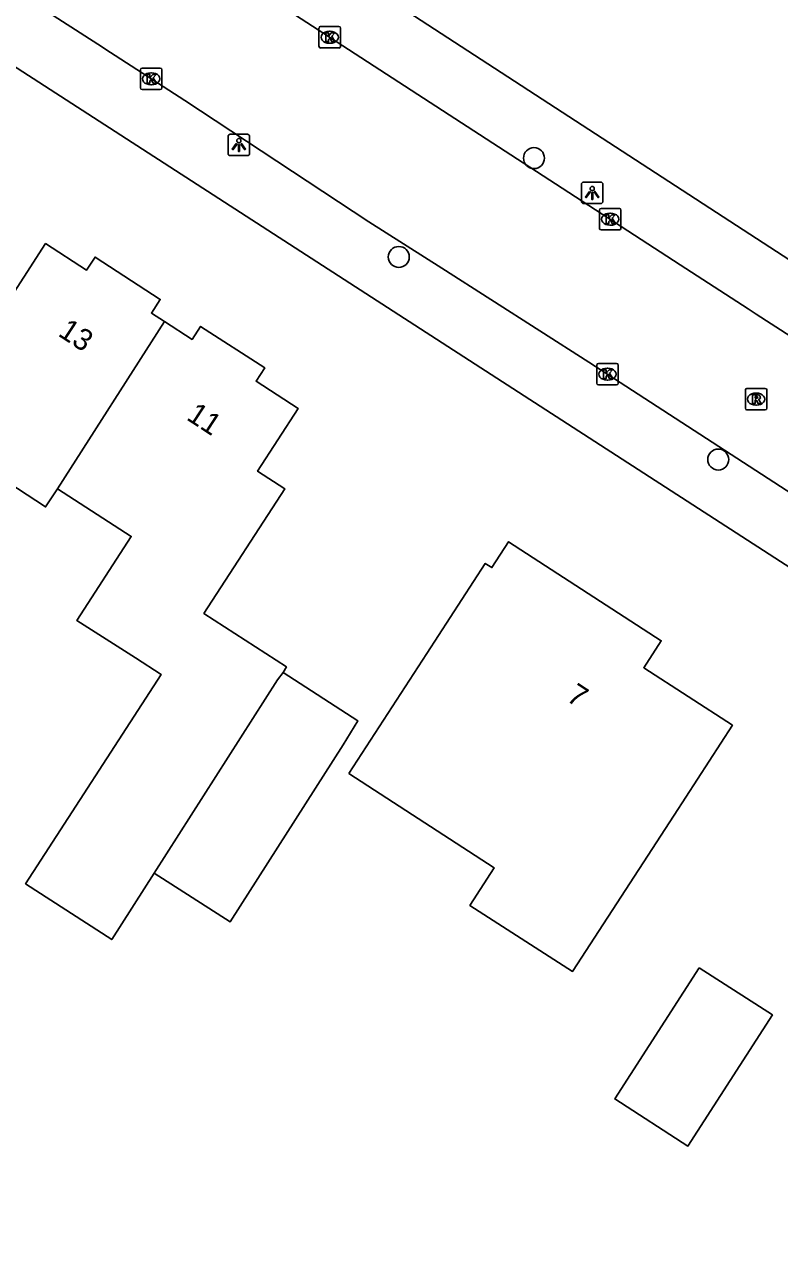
# Model space of a CAD drawing. Extents: x 161141 to 161601, y 381708 to 382245.
# Drawn here: x 161311.4 to 161346.6, y 381911 to 381968.7 of the extents above; entities that cross this region are included whole.
import ezdxf

# ---------------------------------------------------------------- set-up
doc = ezdxf.new("R2010")
doc.units = 0
for name, color, linetype in [('IMGEO_Boom', 7, 'Continuous'), ('IMGEO_Kolk', 7, 'Continuous'), ('IMGEO_Lichtpunt', 7, 'Continuous'), ('IMGEO_Pand', 7, 'Continuous'), ('IMGEO_Pand_nummerreeks', 7, 'Continuous'), ('IMGEO_Rijbaan_lokaal_open', 7, 'Continuous'), ('IMGEO_Rioolput', 7, 'Continuous'), ('IMGEO_Voetpad_open', 7, 'Continuous')]:
    doc.layers.add(name, color=color, linetype=linetype)

msp = doc.modelspace()

# ---------------------------------------------------------------- linework, layer by layer
at = {"layer": 'IMGEO_Boom'}
for centre in [(161335.154, 381962.458), (161328.858, 381957.854), (161343.738, 381948.417)]:
    msp.add_circle(centre, 0.489, dxfattribs=at)
at = {"layer": 'IMGEO_Kolk'}
for p, q in [((161325.141, 381967.662), (161325.141, 381968.514)), ((161325.216, 381968.588), (161326.068, 381968.588)), ((161325.629, 381968.368), (161325.654, 381968.368)), ((161326.142, 381968.514), (161326.142, 381967.662)), ((161325.652, 381967.808), (161325.627, 381967.808)), ((161326.068, 381967.588), (161325.216, 381967.588)), ((161316.898, 381966.652), (161317.75, 381966.652)), ((161316.823, 381965.726), (161316.823, 381966.578)), ((161317.311, 381966.432), (161317.336, 381966.432)), ((161317.824, 381966.578), (161317.824, 381965.726)), ((161317.75, 381965.652), (161316.898, 381965.652)), ((161317.334, 381965.872), (161317.309, 381965.872)), ((161338.203, 381959.187), (161338.203, 381960.039)), ((161338.278, 381960.113), (161339.13, 381960.113)), ((161338.691, 381959.893), (161338.716, 381959.893)), ((161339.204, 381960.039), (161339.204, 381959.187)), ((161338.714, 381959.333), (161338.689, 381959.333)), ((161339.13, 381959.113), (161338.278, 381959.113)), ((161338.077, 381951.969), (161338.077, 381952.821)), ((161338.152, 381952.895), (161339.004, 381952.895)), ((161339.078, 381952.821), (161339.078, 381951.969)), ((161338.565, 381952.675), (161338.59, 381952.675)), ((161339.004, 381951.895), (161338.152, 381951.895)), ((161338.588, 381952.115), (161338.563, 381952.115))]:
    msp.add_line(p, q, dxfattribs=at)
for points in [[(161325.141, 381967.662), (161325.141, 381968.514)], [(161325.216, 381968.588), (161326.068, 381968.588)], [(161326.142, 381968.514), (161326.142, 381967.662)], [(161325.462, 381968.288), (161325.585, 381968.288), (161325.585, 381968.137), (161325.715, 381968.288), (161325.879, 381968.288), (161325.733, 381968.137), (161325.886, 381967.888), (161325.734, 381967.888), (161325.649, 381968.052), (161325.585, 381967.985), (161325.585, 381967.888), (161325.462, 381967.888), (161325.462, 381968.288)], [(161326.068, 381967.588), (161325.216, 381967.588)], [(161316.898, 381966.652), (161317.75, 381966.652)], [(161316.823, 381965.726), (161316.823, 381966.578)], [(161317.144, 381966.352), (161317.267, 381966.352), (161317.267, 381966.201), (161317.397, 381966.352), (161317.561, 381966.352), (161317.415, 381966.201), (161317.568, 381965.952), (161317.416, 381965.952), (161317.331, 381966.116), (161317.267, 381966.049), (161317.267, 381965.952), (161317.144, 381965.952), (161317.144, 381966.352)], [(161317.824, 381966.578), (161317.824, 381965.726)], [(161317.75, 381965.652), (161316.898, 381965.652)], [(161338.203, 381959.187), (161338.203, 381960.039)], [(161338.278, 381960.113), (161339.13, 381960.113)], [(161338.524, 381959.813), (161338.647, 381959.813), (161338.647, 381959.662), (161338.777, 381959.813), (161338.941, 381959.813), (161338.795, 381959.662), (161338.948, 381959.413), (161338.796, 381959.413), (161338.711, 381959.577), (161338.647, 381959.51), (161338.647, 381959.413), (161338.524, 381959.413), (161338.524, 381959.813)], [(161339.204, 381960.039), (161339.204, 381959.187)], [(161339.13, 381959.113), (161338.278, 381959.113)], [(161338.077, 381951.969), (161338.077, 381952.821)], [(161338.152, 381952.895), (161339.004, 381952.895)], [(161339.078, 381952.821), (161339.078, 381951.969)], [(161338.398, 381952.595), (161338.521, 381952.595), (161338.521, 381952.444), (161338.651, 381952.595), (161338.815, 381952.595), (161338.669, 381952.444), (161338.822, 381952.195), (161338.67, 381952.195), (161338.585, 381952.359), (161338.521, 381952.292), (161338.521, 381952.195), (161338.398, 381952.195), (161338.398, 381952.595)], [(161339.004, 381951.895), (161338.152, 381951.895)]]:
    msp.add_lwpolyline(points, dxfattribs=at)
for centre, start, end in [((161325.218, 381968.512), 91.55205, 178.44795), ((161325.218, 381968.512), 91.55205, 178.44795), ((161326.066, 381968.512), 1.55205, 88.44795), ((161326.066, 381968.512), 1.55205, 88.44795), ((161325.218, 381967.664), 181.55205, 268.44795), ((161325.218, 381967.664), 181.55205, 268.44795), ((161326.066, 381967.664), 271.55205, 358.44795), ((161326.066, 381967.664), 271.55205, 358.44795), ((161316.9, 381966.576), 91.55205, 178.44795), ((161316.9, 381966.576), 91.55205, 178.44795), ((161317.748, 381966.576), 1.55205, 88.44795), ((161317.748, 381966.576), 1.55205, 88.44795), ((161316.9, 381965.728), 181.55205, 268.44795), ((161316.9, 381965.728), 181.55205, 268.44795), ((161317.748, 381965.728), 271.55205, 358.44795), ((161317.748, 381965.728), 271.55205, 358.44795), ((161338.28, 381960.037), 91.55205, 178.44795), ((161338.28, 381960.037), 91.55205, 178.44795), ((161339.128, 381960.037), 1.55205, 88.44795), ((161339.128, 381960.037), 1.55205, 88.44795), ((161338.28, 381959.189), 181.55205, 268.44795), ((161338.28, 381959.189), 181.55205, 268.44795), ((161339.128, 381959.189), 271.55205, 358.44795), ((161339.128, 381959.189), 271.55205, 358.44795), ((161338.154, 381952.819), 91.55205, 178.44795), ((161338.154, 381952.819), 91.55205, 178.44795), ((161339.002, 381952.819), 1.55205, 88.44795), ((161339.002, 381952.819), 1.55205, 88.44795), ((161338.154, 381951.971), 181.55205, 268.44795), ((161338.154, 381951.971), 181.55205, 268.44795), ((161339.002, 381951.971), 271.55205, 358.44795), ((161339.002, 381951.971), 271.55205, 358.44795)]:
    msp.add_arc(centre, 0.0765, start, end, dxfattribs=at)
for centre, major_axis, ratio, start_param, end_param in [((161325.628, 381968.088), (-0.387, 0.002), 0.722429, 4.712389, 7.853982), ((161325.653, 381968.088), (-0.39, 0.002), 0.717154, 1.570796, 4.712389), ((161317.31, 381966.152), (-0.387, 0.002), 0.722429, 4.712389, 7.853982), ((161317.335, 381966.152), (-0.39, 0.002), 0.717154, 1.570796, 4.712389), ((161338.69, 381959.613), (-0.387, 0.002), 0.722429, 4.712389, 7.853982), ((161338.715, 381959.613), (-0.39, 0.002), 0.717154, 1.570796, 4.712389), ((161338.564, 381952.395), (-0.387, 0.002), 0.722429, 4.712389, 7.853982), ((161338.589, 381952.395), (-0.39, 0.002), 0.717154, 1.570796, 4.712389)]:
    msp.add_ellipse(centre, major_axis=major_axis, ratio=ratio, start_param=start_param, end_param=end_param, dxfattribs=at)
at = {"layer": 'IMGEO_Lichtpunt'}
for p, q in [((161320.909, 381963.475), (161320.909, 381962.668)), ((161320.909, 381963.475), (161320.909, 381962.668)), ((161321.811, 381963.57), (161321.003, 381963.57)), ((161321.811, 381963.57), (161321.003, 381963.57)), ((161321.905, 381962.668), (161321.905, 381963.475)), ((161321.905, 381962.668), (161321.905, 381963.475)), ((161321.003, 381962.574), (161321.811, 381962.574)), ((161321.003, 381962.574), (161321.811, 381962.574)), ((161337.367, 381961.244), (161337.367, 381960.437)), ((161337.367, 381961.244), (161337.367, 381960.437)), ((161338.269, 381961.339), (161337.461, 381961.339)), ((161338.269, 381961.339), (161337.461, 381961.339)), ((161338.363, 381960.437), (161338.363, 381961.244)), ((161338.363, 381960.437), (161338.363, 381961.244)), ((161337.461, 381960.343), (161338.269, 381960.343)), ((161337.461, 381960.343), (161338.269, 381960.343))]:
    msp.add_line(p, q, dxfattribs=at)
for points in [[(161321.283, 381963.139), (161321.322, 381963.111), (161321.134, 381962.849), (161321.096, 381962.876), (161321.283, 381963.139)], [(161321.385, 381963.091), (161321.432, 381963.091), (161321.432, 381962.769), (161321.385, 381962.769), (161321.385, 381963.091)], [(161321.495, 381963.111), (161321.533, 381963.138), (161321.72, 381962.876), (161321.681, 381962.848), (161321.495, 381963.111)], [(161337.741, 381960.908), (161337.78, 381960.88), (161337.592, 381960.618), (161337.554, 381960.645), (161337.741, 381960.908)], [(161337.953, 381960.88), (161337.991, 381960.907), (161338.178, 381960.645), (161338.139, 381960.617), (161337.953, 381960.88)], [(161337.843, 381960.86), (161337.89, 381960.86), (161337.89, 381960.538), (161337.843, 381960.538), (161337.843, 381960.86)]]:
    msp.add_lwpolyline(points, dxfattribs=at)
for centre in [(161321.408, 381963.273), (161337.866, 381961.042)]:
    msp.add_circle(centre, 0.0994, dxfattribs=at)
for centre, start, end in [((161321.003, 381963.475), 90, 180), ((161321.003, 381963.475), 90, 180), ((161321.811, 381963.475), 0, 90), ((161321.811, 381963.475), 0, 90), ((161321.003, 381962.668), 180, 270), ((161321.003, 381962.668), 180, 270), ((161321.811, 381962.668), 270, 0), ((161321.811, 381962.668), 270, 360), ((161337.461, 381961.244), 90, 180), ((161337.461, 381961.244), 90, 180), ((161338.269, 381961.244), 0, 90), ((161338.269, 381961.244), 0, 90), ((161337.461, 381960.437), 180, 270), ((161337.461, 381960.437), 180, 270), ((161338.269, 381960.437), 270, 0), ((161338.269, 381960.437), 270, 360)]:
    msp.add_arc(centre, 0.0946, start, end, dxfattribs=at)
at = {"layer": 'IMGEO_Pand'}
for points in [[(161296.607, 381946.251), (161297.721, 381948.068), (161300.204, 381951.783), (161303.481, 381949.642), (161305.314, 381952.447), (161307.532, 381950.998), (161307.878, 381951.537), (161309.224, 381953.565), (161312.409, 381958.477), (161314.316, 381957.241), (161314.709, 381957.847), (161317.744, 381955.877), (161317.332, 381955.241), (161317.942, 381954.845)], [(161317.942, 381954.845), (161312.965, 381947.06)], [(161317.942, 381954.845), (161319.229, 381954.011), (161319.625, 381954.622), (161322.611, 381952.686), (161322.208, 381952.066), (161324.177, 381950.789), (161322.283, 381947.869), (161323.542, 381947.053), (161319.778, 381941.251), (161323.627, 381938.754), (161323.465, 381938.504)], [(161312.965, 381947.06), (161312.408, 381946.208), (161309.369, 381948.193), (161306.469, 381943.662), (161301.803, 381946.771), (161298.521, 381941.748), (161298.211, 381942.48)], [(161317.459, 381929.147), (161315.487, 381926.054), (161311.476, 381928.656), (161317.797, 381938.4), (161316.587, 381939.175), (161313.857, 381940.924), (161316.394, 381944.835), (161312.965, 381947.06)], [(161326.534, 381933.789), (161330.165, 381939.387), (161332.886, 381943.581), (161333.193, 381943.382), (161333.975, 381944.588), (161341.086, 381939.976), (161340.269, 381938.717), (161344.399, 381936.038), (161341.679, 381931.844), (161336.953, 381924.571), (161332.168, 381927.644), (161333.306, 381929.397), (161326.534, 381933.789)], [(161323.465, 381938.504), (161326.953, 381936.241), (161326.262, 381935.133), (161321.004, 381926.887), (161317.459, 381929.147)], [(161323.465, 381938.504), (161323.208, 381938.163), (161317.459, 381929.147)], [(161342.846, 381924.74), (161346.258, 381922.545), (161342.328, 381916.436), (161338.915, 381918.631), (161342.846, 381924.74)]]:
    msp.add_lwpolyline(points, dxfattribs=at)
at = {"layer": 'IMGEO_Rijbaan_lokaal_open'}
for points in [[(161278.323, 381991.478), (161299.753, 381977.533), (161307.482, 381972.536), (161311.114, 381970.18), (161315.062, 381967.62), (161315.173, 381967.548), (161318.89, 381965.138), (161327.462, 381959.489), (161330.866, 381957.332), (161337.714, 381952.958), (161346.638, 381947.161), (161350.625, 381944.584), (161357.825, 381939.931), (161366.222, 381934.52), (161372.037, 381930.857), (161375.083, 381928.811)], [(161430.53, 381892.26), (161428.93, 381893.541), (161416.582, 381903.762), (161409.42, 381909.443), (161405.146, 381912.95), (161401.483, 381915.955), (161397.742, 381918.904), (161394.58, 381921.397), (161388.533, 381926.301), (161384.971, 381929.006), (161381.728, 381931.469), (161381.315, 381931.756), (161376.383, 381935.18), (161370.251, 381939.135), (161367.432, 381940.939), (161364.318, 381942.933), (161361.946, 381944.451), (161354.44, 381949.434), (161345.5, 381955.194), (161345.132, 381955.433), (161341.968, 381957.49), (161334.965, 381962.043), (161325.373, 381968.263), (161318.237, 381972.89)]]:
    msp.add_lwpolyline(points, dxfattribs=at)
at = {"layer": 'IMGEO_Rioolput'}
for p, q in [((161345.001, 381950.806), (161345.001, 381951.658)), ((161345.076, 381951.732), (161345.928, 381951.732)), ((161346.002, 381951.658), (161346.002, 381950.806)), ((161345.489, 381951.512), (161345.514, 381951.512)), ((161345.928, 381950.732), (161345.076, 381950.732)), ((161345.512, 381950.952), (161345.487, 381950.952))]:
    msp.add_line(p, q, dxfattribs=at)
for points in [[(161345.001, 381950.806), (161345.001, 381951.658)], [(161345.076, 381951.732), (161345.928, 381951.732)], [(161346.002, 381951.658), (161346.002, 381950.806)], [(161345.59, 381951.43), (161345.338, 381951.432), (161345.338, 381951.032)], [(161345.338, 381951.032), (161345.462, 381951.032), (161345.462, 381951.194), (161345.473, 381951.194)], [(161345.516, 381951.351), (161345.462, 381951.351), (161345.462, 381951.27)], [(161345.462, 381951.27), (161345.514, 381951.27)], [(161345.52, 381951.165), (161345.591, 381951.032), (161345.731, 381951.032), (161345.666, 381951.158)], [(161345.928, 381950.732), (161345.076, 381950.732)]]:
    msp.add_lwpolyline(points, dxfattribs=at)
for centre, radius, start, end in [((161345.078, 381951.656), 0.0765, 91.55205, 178.44795), ((161345.078, 381951.656), 0.0765, 91.55205, 178.44795), ((161345.926, 381951.656), 0.0765, 1.55205, 88.44795), ((161345.926, 381951.656), 0.0765, 1.55205, 88.44795), ((161345.472, 381951.141), 0.0533, 26.02933, 88.69889), ((161345.498, 381951.459), 0.19, 274.7715, 282.96867), ((161345.522, 381951.255), 0.0964, 77.00612, 93.18647), ((161345.536, 381951.312), 0.0378, 276.66336, 79.67722), ((161345.589, 381951.32), 0.109, 350.36119, 89.41601), ((161345.587, 381951.32), 0.112, 277.58423, 350.98172), ((161345.571, 381951.105), 0.108, 29.51342, 73.79051), ((161345.078, 381950.808), 0.0765, 181.55205, 268.44795), ((161345.078, 381950.808), 0.0765, 181.55205, 268.44795), ((161345.926, 381950.808), 0.0765, 271.55205, 358.44795), ((161345.926, 381950.808), 0.0765, 271.55205, 358.44795)]:
    msp.add_arc(centre, radius, start, end, dxfattribs=at)
for centre, major_axis, ratio, start_param, end_param in [((161345.488, 381951.232), (-0.387, 0.002), 0.722429, 4.712389, 7.853982), ((161345.513, 381951.232), (-0.39, 0.002), 0.717154, 1.570796, 4.712389)]:
    msp.add_ellipse(centre, major_axis=major_axis, ratio=ratio, start_param=start_param, end_param=end_param, dxfattribs=at)
at = {"layer": 'IMGEO_Voetpad_open'}
for points in [[(161278.294, 382002.287), (161281.877, 382000), (161299.823, 381988.353), (161310.674, 381981.109), (161322.611, 381973.432), (161322.712, 381973.551), (161378.924, 381936.994), (161385.641, 381932.206), (161392.817, 381926.552), (161429.313, 381896.994)], [(161370.462, 381928.258), (161276.309, 381989.126)]]:
    msp.add_lwpolyline(points, dxfattribs=at)

# ---------------------------------------------------------------- texts
at = {"layer": 'IMGEO_Pand_nummerreeks'}
for s, rotation, p in [('13', 326.84293, (161312.942, 381954.211)), ('11', 326.84293, (161318.921, 381950.305)), ('7', 326.76829, (161336.615, 381937.217))]:
    msp.add_text(s, height=1, rotation=rotation, dxfattribs=at).set_placement(p)

doc.saveas('drawing.dxf')
